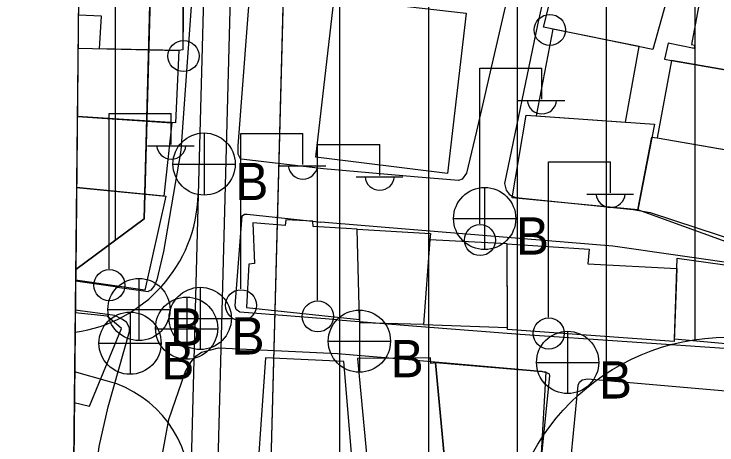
# Model space of a CAD drawing. Extents: x 417997 to 421451, y 4451742 to 4455216.
# Drawn here: x 419108.7 to 419187.8, y 4452874.4 to 4452922.9 of the extents above; entities that cross this region are included whole.
import ezdxf

# ---------------------------------------------------------------- set-up
doc = ezdxf.new("R2010")
doc.units = 0
for name, color, linetype in [('ADAKENARI', 7, 'Continuous'), ('B_Mesken', 7, 'Continuous'), ('KALDIRIM', 7, 'Continuous'), ('PAFTALAMA', 7, 'Continuous'), ('PL_KON_MEV_350', 7, 'Continuous'), ('S_Elektrik_Diregi', 7, 'Continuous'), ('S_Rogar_Kapagi', 7, 'Continuous'), ('S_Rogar_Kapagi_Buski', 7, 'Continuous'), ('SM_DAIRE', 7, 'Continuous'), ('SN_3_DERECE_KAYNAK_KORUMA', 7, 'Continuous'), ('TR_ORTAYOGUNKONUT', 7, 'Continuous'), ('Y_Lejant', 7, 'Continuous'), ('Yol_Sose', 7, 'Continuous')]:
    doc.layers.add(name, color=color, linetype=linetype)

msp = doc.modelspace()

# ---------------------------------------------------------------- linework, layer by layer
at = {"layer": 'ADAKENARI'}
for p, q in [((419125.015, 4452962.317), (419123.365, 4452899.906)), ((419125.015, 4452962.317), (419123.365, 4452899.906)), ((419135.391, 4452787.233), (419139.641, 4452947.996)), ((419135.391, 4452787.233), (419139.641, 4452947.996)), ((419123.365, 4452899.906), (419115.662, 4452894.206)), ((419123.365, 4452899.906), (419115.662, 4452894.206))]:
    msp.add_line(p, q, dxfattribs=at)
at = {"layer": 'B_Mesken'}
for points in [[(419182.831, 4452926.899), (419180.622, 4452918.955), (419168.299, 4452921.442), (419170.243, 4452929.244)], [(419195.297, 4452915.515), (419196.712, 4452924.558), (419186.256, 4452926.364), (419184.969, 4452919.522), (419185.315, 4452919.417), (419185.262, 4452919.071), (419182.319, 4452919.666), (419181.932, 4452917.847), (419182.699, 4452917.719)], [(419144.729, 4452924.754), (419159.61, 4452923.04), (419157.52, 4452904.988), (419142.674, 4452906.824)], [(419169.351, 4452921.229), (419167.463, 4452911.48), (419177.548, 4452910.773), (419179.087, 4452919.264)], [(419181.114, 4452909.019), (419194.113, 4452906.759), (419195.612, 4452915.46), (419182.699, 4452917.719)], [(419180.785, 4452910.546), (419178.927, 4452900.911), (419164.779, 4452902.239), (419166.356, 4452911.558)], [(419193.405, 4452906.882), (419191.459, 4452896.375), (419178.927, 4452900.911), (419180.5, 4452909.07), (419181.114, 4452909.019)], [(419134.868, 4452889.894), (419147.594, 4452888.569), (419147.351, 4452898.745), (419142.37, 4452899.015), (419142.355, 4452899.638), (419139.294, 4452899.783), (419139.223, 4452899.126), (419135.609, 4452899.445), (419135.767, 4452894.859), (419135.144, 4452894.791)], [(419147.351, 4452898.745), (419155.59, 4452898.247), (419155.503, 4452897.541), (419154.784, 4452887.985), (419147.664, 4452888.195), (419147.594, 4452888.569)], [(419164.225, 4452897.067), (419155.503, 4452897.541), (419154.784, 4452887.985), (419164.263, 4452887.68)], [(419164.225, 4452897.067), (419173.459, 4452896.467), (419173.298, 4452894.844), (419183.32, 4452894.301), (419183.026, 4452886.088), (419164.264, 4452887.432)], [(419183.32, 4452894.301), (419183.358, 4452895.467), (419191.953, 4452894.263), (419191.29, 4452885.597), (419183.035, 4452886.355)], [(419136.224, 4452873.001), (419146.768, 4452872.61), (419145.835, 4452883.828), (419137.022, 4452884.239)], [(419156.155, 4452883.702), (419155.609, 4452883.611), (419155.603, 4452884.235), (419147.385, 4452884.177), (419148.487, 4452872.239), (419157.212, 4452872.063), (419157.144, 4452873.285)], [(419167.054, 4452872.881), (419168.027, 4452872.795), (419168.619, 4452882.645), (419156.155, 4452883.702), (419157.144, 4452873.285), (419158.569, 4452873.293)]]:
    msp.add_lwpolyline(points, close=True, dxfattribs=at)
for points in [[(419116.016, 4452927.138), (419127.804, 4452926.77), (419127.703, 4452918.926), (419127.256, 4452918.845), (419118.348, 4452919.027), (419118.563, 4452922.695), (419115.97, 4452922.79)], [(419115.93, 4452919.077), (419127.256, 4452918.845), (419126.882, 4452910.677), (419115.848, 4452911.389)], [(419115.848, 4452911.389), (419126.484, 4452910.703), (419125.565, 4452902.445), (419115.762, 4452903.399)], [(419115.762, 4452903.399), (419125.789, 4452902.423), (419123.436, 4452891.874), (419115.651, 4452892.995)], [(419115.503, 4452879.207), (419117.201, 4452878.798), (419120.823, 4452887.553), (419119.217, 4452888.927), (419115.611, 4452889.31)]]:
    msp.add_lwpolyline(points, dxfattribs=at)
at = {"layer": 'KALDIRIM'}
for p, q in [((419130.638, 4452948.011), (419129.438, 4452902.604)), ((419130.638, 4452948.011), (419129.438, 4452902.604)), ((419133.635, 4452947.832), (419129.393, 4452787.39)), ((419133.635, 4452947.832), (419129.393, 4452787.39)), ((419129.438, 4452902.604), (419126.394, 4452787.47)), ((419129.438, 4452902.604), (419126.394, 4452787.47)), ((419119.24, 4452881.64), (419115.538, 4452882.665)), ((419119.24, 4452881.64), (419115.538, 4452882.665))]:
    msp.add_line(p, q, dxfattribs=at)
for centre, radius, start, end in [((419113.392, 4452903.028), 16.052, 277.85785, 358.48545), ((419113.392, 4452903.028), 16.052, 277.85785, 358.48545), ((419115.848, 4452869.394), 12.707, 358.48545, 74.5201), ((419115.848, 4452869.394), 12.707, 358.48545, 74.5201)]:
    msp.add_arc(centre, radius, start, end, dxfattribs=at)
at = {"layer": 'PAFTALAMA'}
msp.add_line((419138.441, 4455021.891), (419108.72, 4452245.779), dxfattribs=at)
msp.add_line((419138.441, 4455021.891), (419108.72, 4452245.779), dxfattribs=at)
at = {"layer": 'PL_KON_MEV_350'}
msp.add_line((419117.291, 4453046.386), (419115.662, 4452894.206), dxfattribs=at)
for points in [[(419135.391, 4452787.233), (419139.641, 4452947.996), (419166.334, 4452946.426), (419187.355, 4453014.338), (419163.538, 4453023.756), (419163.539, 4453023.756), (419189.133, 4453054.097), (419205.392, 4453059.806), (419235.442, 4453053.881), (419229.153, 4453037.371), (419259.796, 4453026.004), (419268.199, 4453043.302), (419296.653, 4453034.642), (419293.317, 4453023.624), (419257.841, 4452906.471), (419231.013, 4452817.876)], [(419115.662, 4452894.206), (419123.365, 4452899.906), (419125.015, 4452962.317), (419125.417, 4452969.354), (419126.249, 4452976.353), (419127.509, 4452983.288), (419129.191, 4452990.133), (419131.29, 4452996.862), (419133.796, 4453003.45), (419136.702, 4453009.871), (419139.995, 4453016.103), (419143.664, 4453022.121), (419147.695, 4453027.903), (419152.073, 4453033.428), (419154.645, 4453036.476), (419139.075, 4453044.969), (419117.291, 4453046.386)]]:
    msp.add_lwpolyline(points, dxfattribs=at)
at = {"layer": 'S_Elektrik_Diregi'}
for p, q in [((419127.759, 4452920.042), (419127.759, 4452937.542)), ((419161.124, 4452899.34), (419161.124, 4452916.84)), ((419161.124, 4452916.84), (419168.124, 4452916.84)), ((419168.124, 4452913.34), (419168.124, 4452916.84)), ((419165.464, 4452913.2), (419170.714, 4452913.2)), ((419119.41, 4452894.257), (419119.41, 4452911.757)), ((419119.41, 4452911.757), (419126.41, 4452911.757)), ((419126.41, 4452908.257), (419126.41, 4452911.757)), ((419134.225, 4452891.997), (419134.225, 4452909.497)), ((419134.225, 4452909.497), (419141.225, 4452909.497)), ((419141.225, 4452905.997), (419141.225, 4452909.497)), ((419123.75, 4452908.117), (419129, 4452908.117)), ((419142.872, 4452890.752), (419142.872, 4452908.252)), ((419142.872, 4452908.252), (419149.872, 4452908.252)), ((419149.872, 4452904.752), (419149.872, 4452908.252)), ((419168.861, 4452888.822), (419168.861, 4452906.322)), ((419168.861, 4452906.322), (419175.861, 4452906.322)), ((419175.861, 4452902.822), (419175.861, 4452906.322)), ((419138.565, 4452905.857), (419143.815, 4452905.857)), ((419147.212, 4452904.612), (419152.462, 4452904.612)), ((419173.201, 4452902.682), (419178.451, 4452902.682))]:
    msp.add_line(p, q, dxfattribs=at)
for centre in [(419169.019, 4452921.14), (419127.795, 4452918.206), (419161.16, 4452897.504), (419119.446, 4452892.421), (419134.261, 4452890.161), (419142.908, 4452888.917), (419168.897, 4452886.987)]:
    msp.add_circle(centre, 1.75, dxfattribs=at)
for centre in [(419168.125, 4452913.353), (419126.41, 4452908.269), (419141.226, 4452906.01), (419149.873, 4452904.765), (419175.861, 4452902.835)]:
    msp.add_arc(centre, 1.658, 184.83843, 355.14641, dxfattribs=at)
at = {"layer": 'S_Rogar_Kapagi'}
for p, q in [((419128.196, 4452884.055), (419128.196, 4452891.055)), ((419124.625, 4452887.52), (419131.626, 4452887.52))]:
    msp.add_line(p, q, dxfattribs=at)
msp.add_circle((419128.142, 4452887.583), 3.5, dxfattribs=at)
at = {"layer": 'S_Rogar_Kapagi_Buski'}
for p, q in [((419130.105, 4452909.555), (419130.105, 4452902.555)), ((419126.605, 4452906.055), (419133.605, 4452906.055)), ((419161.685, 4452903.425), (419161.685, 4452896.425)), ((419158.185, 4452899.925), (419165.185, 4452899.925)), ((419122.775, 4452893.185), (419122.775, 4452886.185)), ((419129.675, 4452892.185), (419129.675, 4452885.185)), ((419119.275, 4452889.685), (419126.275, 4452889.685)), ((419121.775, 4452889.395), (419121.775, 4452882.395)), ((419147.585, 4452889.625), (419147.585, 4452882.625)), ((419126.175, 4452888.685), (419133.175, 4452888.685)), ((419171.024, 4452887.235), (419171.024, 4452880.235)), ((419118.275, 4452885.895), (419125.275, 4452885.895)), ((419144.085, 4452886.125), (419151.085, 4452886.125)), ((419167.524, 4452883.735), (419174.524, 4452883.735))]:
    msp.add_line(p, q, dxfattribs=at)
for centre in [(419130.105, 4452906.055), (419161.685, 4452899.925), (419122.775, 4452889.685), (419129.675, 4452888.685), (419121.775, 4452885.895), (419147.585, 4452886.125), (419171.024, 4452883.735)]:
    msp.add_circle(centre, 3.5, dxfattribs=at)
at = {"layer": 'SM_DAIRE'}
msp.add_circle((419189.036, 4452861.556), 25, dxfattribs=at)
msp.add_circle((419189.036, 4452861.556), 25, dxfattribs=at)
at = {"layer": 'SN_3_DERECE_KAYNAK_KORUMA'}
msp.add_line((419126.495, 4453906.073), (419108.72, 4452245.779), dxfattribs=at)
msp.add_line((419126.495, 4453906.073), (419108.72, 4452245.779), dxfattribs=at)
at = {"layer": 'TR_ORTAYOGUNKONUT'}
for p, q in [((419120.129, 4452897.511), (419120.129, 4453046.201)), ((419120.129, 4452897.511), (419120.129, 4453046.201)), ((419185.391, 4452886.289), (419185.391, 4453007.993)), ((419185.391, 4452886.289), (419185.391, 4453007.993)), ((419175.391, 4452882.504), (419175.391, 4452975.686)), ((419175.391, 4452882.504), (419175.391, 4452975.686)), ((419145.391, 4452764.109), (419145.391, 4452947.657)), ((419145.391, 4452764.109), (419145.391, 4452947.657)), ((419155.391, 4452758.132), (419155.391, 4452947.069)), ((419155.391, 4452758.132), (419155.391, 4452947.069)), ((419165.391, 4452869.674), (419165.391, 4452946.481)), ((419165.391, 4452869.674), (419165.391, 4452946.481))]:
    msp.add_line(p, q, dxfattribs=at)
at = {"layer": 'Y_Lejant'}
msp.add_lwpolyline([(419138.442, 4455021.89), (421266.409, 4454999.402), (421237.471, 4452223.294), (419108.722, 4452245.778)], close=True, dxfattribs=at)
at = {"layer": 'Yol_Sose'}
for points in [[(419154.97, 4453017.734), (419157.445, 4453021.48), (419160.108, 4453025.348), (419160.824, 4453025.713), (419161.644, 4453025.799), (419162.027, 4453025.711), (419183.827, 4453016.671), (419184.244, 4453016.374), (419184.678, 4453015.675), (419184.78, 4453014.995), (419184.777, 4453014.088), (419180.018, 4452993.265), (419169.404, 4452947.226), (419160.753, 4452909.75), (419159.657, 4452905.024), (419159.166, 4452904.345), (419158.747, 4452904.206), (419153.759, 4452904.632)], [(419143.548, 4452905.505), (419134.277, 4452906.589), (419134.219, 4452906.63), (419133.957, 4452907.156), (419133.948, 4452908.112), (419136.093, 4452936.089), (419136.885, 4452947.577), (419137.006, 4452949.485), (419135.69, 4452966.609), (419134.698, 4452983.286), (419134.739, 4452983.962), (419135.145, 4452984.806), (419140.677, 4452994.982), (419149.787, 4453009.891)], [(419186.775, 4453004.776), (419182.405, 4452986.458), (419177.469, 4452966.046), (419173.147, 4452946.435), (419167.639, 4452921.713), (419163.899, 4452903.865), (419164.106, 4452903.114), (419164.436, 4452902.66), (419164.697, 4452902.485), (419165.203, 4452902.296), (419178.416, 4452900.926), (419180.313, 4452900.591), (419190.715, 4452897.171), (419191.098, 4452897.171), (419191.5, 4452897.449), (419193.646, 4452909.433), (419197.396, 4452930.109), (419200.522, 4452946.667), (419202.853, 4452960.556), (419207.897, 4452987.391), (419209.322, 4452996.028)], [(419116.2, 4452944.258), (419128.345, 4452944), (419128.86, 4452943.925), (419129.526, 4452943.548), (419129.735, 4452943.243), (419129.959, 4452942.161), (419127.499, 4452907.562), (419125.557, 4452896.227), (419124.796, 4452893.043), (419124.515, 4452892.374), (419124.1, 4452891.868), (419123.816, 4452891.717)], [(419153.757, 4452904.632), (419143.548, 4452905.505)], [(419153.757, 4452904.632), (419153.757, 4452904.632)], [(419153.759, 4452904.632), (419153.757, 4452904.632)], [(419145.143, 4452888.521), (419134.113, 4452889.396), (419133.704, 4452889.687), (419133.618, 4452890.108), (419134.405, 4452900.241), (419134.67, 4452900.413), (419134.969, 4452900.424), (419141.98, 4452899.656), (419142.356, 4452899.615)], [(419142.356, 4452899.615), (419143.265, 4452899.516)], [(419153.693, 4452898.658), (419143.265, 4452899.516)], [(419153.579, 4452887.859), (419165.678, 4452886.909), (419189.78, 4452885.254), (419190.511, 4452885.287), (419190.826, 4452885.53), (419191.053, 4452885.756), (419191.932, 4452893.679), (419191.881, 4452894.219), (419191.708, 4452894.516), (419191.256, 4452894.656), (419176.102, 4452896.814), (419153.695, 4452898.657)], [(419153.693, 4452898.658), (419153.693, 4452898.658)], [(419153.695, 4452898.657), (419153.693, 4452898.658)], [(419120.364, 4452892.194), (419115.65, 4452892.874)], [(419120.343, 4452892.197), (419123.816, 4452891.717)], [(419142.543, 4452792.349), (419141.639, 4452799.109), (419140.818, 4452802.04), (419131.524, 4452829.371), (419130.835, 4452830.844), (419119.336, 4452843.682), (419118.332, 4452845.284), (419117.633, 4452847.096), (419117.266, 4452848.66), (419116.976, 4452850.162), (419116.763, 4452852.179), (419116.845, 4452854.726), (419118.048, 4452872.116), (419118.317, 4452874.259), (419119.3, 4452878.751), (419121.707, 4452887.225), (419121.7, 4452887.623), (419121.362, 4452888.251), (419120.855, 4452888.604), (419120.072, 4452889.025), (419115.615, 4452889.63)], [(419145.143, 4452888.521), (419147.571, 4452888.33), (419153.577, 4452887.859)], [(419153.577, 4452887.859), (419153.578, 4452887.859)], [(419153.578, 4452887.859), (419153.579, 4452887.859)], [(419137.677, 4452835.106), (419137.493, 4452835.252), (419128.546, 4452842.38), (419127.361, 4452843.618), (419126.322, 4452845.31), (419125.903, 4452846.568), (419125.378, 4452848.572), (419124.685, 4452858.886), (419124.955, 4452867.859), (419125.471, 4452873.634), (419126.137, 4452877.307), (419127.995, 4452882.627), (419128.646, 4452883.809), (419129.192, 4452884.448), (419129.819, 4452884.888), (419130.856, 4452885.163), (419131.716, 4452885.377), (419145.106, 4452884.734)], [(419145.106, 4452884.734), (419151.784, 4452884.158)], [(419151.784, 4452884.158), (419153.536, 4452884.006)], [(419153.536, 4452884.006), (419153.537, 4452884.006)], [(419153.537, 4452884.006), (419153.538, 4452884.006)], [(419153.538, 4452884.006), (419168.092, 4452882.75), (419168.732, 4452882.56), (419168.958, 4452882.437), (419168.974, 4452882.211), (419168.06, 4452872.975)], [(419171.424, 4452873.086), (419172.2, 4452881.184), (419172.34, 4452881.497), (419172.672, 4452881.775), (419173.299, 4452881.878), (419189.241, 4452880.501), (419189.797, 4452880.239), (419190.038, 4452879.629), (419190.036, 4452878.81), (419183.98, 4452822.211), (419183.804, 4452821.637), (419180.135, 4452811.466), (419179.961, 4452811.379), (419179.857, 4452811.38), (419161.331, 4452821.205), (419152.914, 4452825.669)]]:
    msp.add_lwpolyline(points, dxfattribs=at)

# ---------------------------------------------------------------- texts
at = {"layer": 'S_Rogar_Kapagi_Buski'}
for p in [(419133.605, 4452901.991), (419165.185, 4452895.861), (419126.275, 4452885.62), (419133.175, 4452884.62), (419151.085, 4452882.06), (419125.275, 4452881.83), (419174.524, 4452879.67)]:
    msp.add_text('B', height=4.2, dxfattribs=at).set_placement(p)

doc.saveas('drawing.dxf')
